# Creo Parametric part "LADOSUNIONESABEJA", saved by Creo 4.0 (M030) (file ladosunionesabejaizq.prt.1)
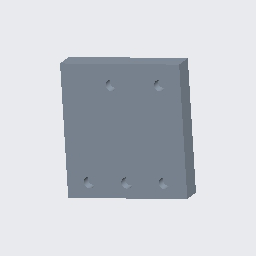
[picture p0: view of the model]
Units: millimeter Newton Second (mmNs); MM, TONNE, SECS

Created from: MMNS_PART_SOLID.PRT

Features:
  1. datum plane "RIGHT"
  2. datum plane "TOP"
  3. datum plane "FRONT"
  4. coordinate system
  5. sketch "Sketch 1"
  6. extrusion "Extrude 1"
  7. pattern "Pattern 1"
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
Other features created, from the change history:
  hole "Hole 1"
  hole "Hole 1 [2]"
  hole "Hole 1 [3]"
  hole "Hole 2"
  pattern "Patrón 2"
  hole "Taladro 2 [2]"
  hole "Hole 3"
  pattern "Pattern 3"
  hole "Hole 3 [2]"

Surfaces: 13 plane, 7 cylinder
